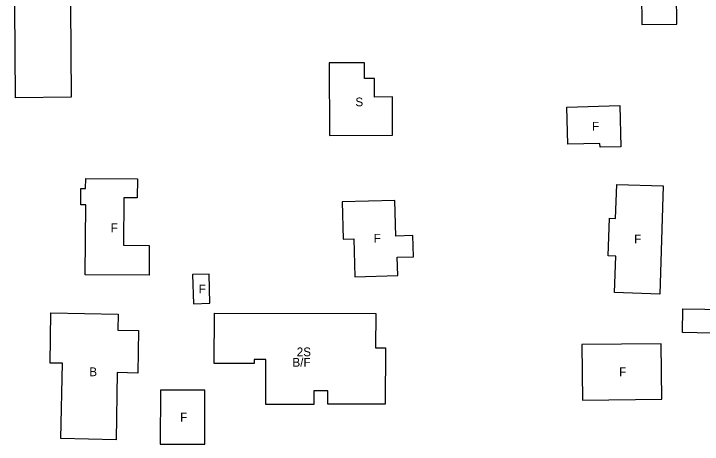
# Model space of a CAD drawing. Extents: x 1304270 to 1306561, y 1876019 to 1876752.
# Drawn here: x 1305661.4 to 1306055.3, y 1876019.5 to 1876265.9 of the extents above; entities that cross this region are included whole.
import ezdxf

# ---------------------------------------------------------------- set-up
doc = ezdxf.new("R2010")
doc.units = 0
doc.layers.add('S_BUILDING', color=7, linetype='Continuous')
doc.layers.add('S_BUILDING_ANNOT', color=7, linetype='Continuous')

msp = doc.modelspace()

# ---------------------------------------------------------------- linework, layer by layer
at = {"layer": 'S_BUILDING'}
for points in [[(1305662.34, 1876217.81), (1305661.36, 1876348.7), (1305693.3, 1876348.94), (1305694.28, 1876218.05)], [(1306020.3, 1876294.98), (1306020.68, 1876259.62), (1306040.74, 1876259.83), (1306040.36, 1876295.2)], [(1305841.9, 1876237.72), (1305842.04, 1876196.17), (1305878.06, 1876196.29), (1305877.99, 1876218.23), (1305867.85, 1876218.2), (1305867.81, 1876228.78), (1305862.12, 1876228.76), (1305862.09, 1876237.79)], [(1305977.8, 1876212.4), (1306008.12, 1876213.25), (1306008.77, 1876189.76), (1305996.86, 1876189.43), (1305996.8, 1876191.64), (1305978.4, 1876191.13)], [(1305724.27, 1876160.58), (1305724.08, 1876133.33), (1305738.93, 1876133.23), (1305738.81, 1876116.17), (1305702.24, 1876116.42), (1305702.51, 1876156.4), (1305699.72, 1876156.42), (1305699.79, 1876165.9), (1305702.5, 1876165.88), (1305702.53, 1876171.63), (1305732.14, 1876171.43), (1305732.06, 1876160.53)], [(1306033.04, 1876167.33), (1306031, 1876105.39), (1306005.2, 1876106.24), (1306005.89, 1876127.13), (1306001.5, 1876127.27), (1306002.22, 1876148.88), (1306005.72, 1876148.76), (1306006.36, 1876168.21)], [(1305849.33, 1876158.18), (1305849.9, 1876136.85), (1305855.98, 1876137.01), (1305856.56, 1876115.35), (1305881.05, 1876116.01), (1305880.76, 1876126.53), (1305890.03, 1876126.78), (1305889.7, 1876138.87), (1305879.95, 1876138.61), (1305879.4, 1876158.99)], [(1305763.73, 1876116.53), (1305764.18, 1876099.9), (1305773.56, 1876100.15), (1305773.11, 1876116.78)], [(1305720.62, 1876060.43), (1305719.91, 1876022.06), (1305688.35, 1876022.65), (1305689.16, 1876065.81), (1305682.13, 1876065.94), (1305682.66, 1876094.64), (1305721.05, 1876093.93), (1305720.88, 1876084.69), (1305732.71, 1876084.47), (1305732.26, 1876060.21)], [(1305776.07, 1876065.73), (1305776.13, 1876094.5), (1305868.45, 1876094.32), (1305868.41, 1876074.71), (1305874, 1876074.69), (1305873.93, 1876042.4), (1305841.09, 1876042.47), (1305841.11, 1876050.04), (1305833.09, 1876050.06), (1305833.07, 1876042.2), (1305805.62, 1876042.26), (1305805.67, 1876068.01), (1305798.85, 1876068.03), (1305798.84, 1876065.69)], [(1306044.25, 1876097.05), (1306069.37, 1876096.57), (1306069.11, 1876082.9), (1306043.99, 1876083.38)], [(1306031.81, 1876076.96), (1305986.42, 1876076.53), (1305986.71, 1876044.78), (1306032.11, 1876045.2)], [(1305745.33, 1876050.47), (1305745.21, 1876019.56), (1305770.67, 1876019.46), (1305770.78, 1876050.38)]]:
    msp.add_lwpolyline(points, close=True, dxfattribs=at)

# ---------------------------------------------------------------- texts
at = {"layer": 'S_BUILDING_ANNOT'}
for s, p in [('S', (1305856.84, 1876212.89)), ('F', (1305992.22, 1876198.98)), ('F', (1305716.81, 1876140.81)), ('F', (1305867.35, 1876134.89)), ('F', (1306016.36, 1876134.46)), ('F', (1305767.21, 1876105.84)), ('2S', (1305823.28, 1876069.84)), ('B/F', (1305820.82, 1876063.84)), ('B', (1305704.59, 1876058.42)), ('F', (1306007.77, 1876058.39)), ('F', (1305756.56, 1876032.47))]:
    msp.add_text(s, height=5, dxfattribs=at).set_placement(p)

doc.saveas('drawing.dxf')
